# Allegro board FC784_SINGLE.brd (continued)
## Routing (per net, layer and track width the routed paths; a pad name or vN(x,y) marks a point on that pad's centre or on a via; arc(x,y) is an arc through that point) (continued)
IO299: length 3
  TOP w0.127: U1.AC2 41.81,50.23 39.5,50.23
IO300: length 4.4
  TOP w0.254: U1.AC3 v1(42.81,50.23)
  L3_SIG1 w0.102: v1(42.81,50.23) 39.11,50.23
IO301: length 5.6
  TOP w0.254: U1.AC4 v1(43.81,50.23)
  L3_SIG1 w0.102: v1(43.81,50.23) 43.31,49.73 39.11,49.73
IO302: length 7.5
  TOP w0.254: U1.AC6 v1(45.81,50.23)
  L4_SIG2 w0.102: 39.26,49.73 45.02,49.73 45.52,50.23 v1(45.81,50.23)
IO303: length 8.7
  TOP w0.254: U1.AC7 v1(46.81,50.23)
  L4_SIG2 w0.102: 40.49,47.73 45.02,47.73 45.31,48.03 45.31,48.44 45.61,48.73 46.02,48.73 46.31,49.03 46.31,49.44 46.81,49.94 v1(46.81,50.23)
IO304: length 9.5
  TOP w0.254: U1.AC8 v1(47.81,50.23)
  L4_SIG2 w0.102: v1(47.81,50.23) 47.31,49.73 47.31,49.03 47.02,48.73 46.61,48.73 46.31,48.44 46.31,48.03 46.02,47.73 45.61,47.73 45.31,47.44 45.31,46.16 44.62,45.46 44.62,43.23
IO305: length 7.9
  TOP w0.254: U1.AC9 v1(48.81,50.23)
  L4_SIG2 w0.102: 48.31,43.26 48.31,49.73 v1(48.81,50.23)
IO306: length 7.6
  TOP w0.254: U1.AC11 v1(50.81,50.23)
  L5_SIG3 w0.102: v1(50.81,50.23) 50.31,49.73 50.31,45.9 50.84,45.38 50.84,43.77
IO307: length 7.8
  TOP w0.254: U1.AC12 v1(51.81,50.23)
  L4_SIG2 w0.102: 51.31,43.33 51.31,49.73 v1(51.81,50.23)
IO308: length 10.2
  TOP w0.254: U1.AC13 v1(52.81,50.23)
  L4_SIG2 w0.102: 54.31,41.84 54.31,49.47 54.05,49.73 53.31,49.73 v1(52.81,50.23)
IO309: length 9.2
  TOP w0.254: U1.AC14 v1(53.81,50.23)
  L4_SIG2 w0.102: v1(53.81,50.23) 54.77,50.23 55.31,49.69 55.31,46.17 56.07,45.41 56.07,43.23
IO310: length 8
  TOP w0.254: U1.AC16 v1(56.81,50.23)
  L4_SIG2 w0.102: v1(56.81,50.23) 56.31,49.73 56.31,46.09 56.73,45.67 56.73,43.28
IO311: length 8.4
  TOP w0.254: U1.AC17 v1(57.81,50.23)
  L5_SIG3 w0.102: 57.31,42.79 57.31,49.73 v1(57.81,50.23)
IO312: length 8.1
  TOP w0.254: U1.AC18 v1(58.81,50.23)
  L5_SIG3 w0.102: 59.31,43.08 59.31,49.52 58.81,50.02 v1(58.81,50.23)
IO313: length 9
  TOP w0.254: U1.AC19 v1(59.81,50.23)
  L4_SIG2 w0.102: v1(59.81,50.23) 60.31,49.73 60.31,48.03 60.61,47.73 61.02,47.73 61.31,47.44 61.31,42.84
IO314: length 8.4
  TOP w0.254: U1.AC21 v1(61.81,50.23)
  L4_SIG2 w0.102: v1(61.81,50.23) 62.31,49.73 62.31,48.03 62.61,47.73 63.02,47.73 63.31,47.44 63.31,43.44
IO315: length 1.8
  TOP w0.127: U1.AD1 39.5,49.73
IO316: length 4.6
  TOP w0.254: U1.AD3 v1(42.81,49.23)
  L3_SIG1 w0.102: v1(42.81,49.23) 42.52,49.23 41.97,48.69 39.11,48.69
IO317: length 5.8
  TOP w0.254: U1.AD4 v1(43.81,49.23)
  L3_SIG1 w0.102: v1(43.81,49.23) 43.53,49.23 43.03,48.73 42.58,48.73 42.07,48.22 39.11,48.22
IO318: length 7.5
  TOP w0.254: U1.AD5 v1(44.81,49.23)
  L3_SIG1 w0.102: v1(44.81,49.23) 44.31,48.73 43.61,48.73 43.31,48.43 43.31,43.43
IO319: length 7
  TOP w0.254: U1.AD6 v1(45.81,49.23)
  L3_SIG1 w0.102: 45.84,43.37 45.84,45.49 45.31,46.02 45.31,48.73 v1(45.81,49.23)
IO320: length 6.8
  TOP w0.254: U1.AD8 v1(47.81,49.23)
  L4_SIG2 w0.102: v1(47.81,49.23) 47.81,48.94 47.31,48.44 47.31,43.33
IO321: length 6.8
  TOP w0.254: U1.AD9 v1(48.81,49.23)
  L3_SIG1 w0.102: v1(48.81,49.23) 49.31,48.74 49.31,43.31
IO322: length 6.8
  TOP w0.254: U1.AD10 v1(49.81,49.23)
  L4_SIG2 w0.102: v1(49.81,49.23) 49.31,48.73 49.31,43.33
IO323: length 7.1
  TOP w0.254: U1.AD11 v1(50.81,49.23)
  L4_SIG2 w0.102: 50.89,43.27 50.89,45.48 50.31,46.06 50.31,48.73 v1(50.81,49.23)
IO324: length 6.8
  TOP w0.254: U1.AD13 v1(52.81,49.23)
  L4_SIG2 w0.102: v1(52.81,49.23) 53.31,48.73 53.31,43.33
IO325: length 6.7
  TOP w0.254: U1.AD14 v1(53.81,49.23)
  L3_SIG1 w0.102: v1(53.81,49.23) 54.31,48.74 54.31,43.41
IO326: length 7
  TOP w0.254: U1.AD15 v1(55.81,49.23)
  L3_SIG1 w0.102: v1(55.81,49.23) 55.32,48.74 55.32,47.03 55.89,46.46 55.89,43.35
IO327: length 6.8
  TOP w0.254: U1.AD16 v1(56.81,49.23)
  L4_SIG2 w0.102: v1(56.81,49.23) 57.31,48.73 57.31,43.33
IO328: length 7.5
  TOP w0.254: U1.AD18 v1(58.81,49.23)
  L4_SIG2 w0.102: 59.31,43.33 59.31,47.44 59.02,47.73 58.61,47.73 58.31,48.02 58.31,48.73 v1(58.81,49.23)
IO329: length 7.7
  TOP w0.254: U1.AD19 v1(59.81,49.23)
  L4_SIG2 w0.102: 59.75,43.33 59.75,46.34 60.31,46.9 60.31,47.44 60.02,47.73 59.61,47.73 59.31,48.02 59.31,48.73 v1(59.81,49.23)
IO330: length 7
  TOP w0.254: U1.AD20 v1(60.81,49.23)
  L3_SIG1 w0.102: v1(60.81,49.23) 60.32,48.74 60.32,46.22 60.88,45.66 60.88,43.39
IO331: length 7.6
  TOP w0.254: U1.AD21 v1(61.81,49.23)
  L3_SIG1 w0.102: 63.51,43.33 63.51,47.31 63.09,47.73 62.61,47.73 62.31,48.03 62.31,48.73 v1(61.81,49.23)
IO332: length 1.8
  TOP w0.127: U1.AE1 39.5,48.73
IO333: length 3
  TOP w0.127: U1.AE2 41.81,48.23 39.5,48.23
IO334: length 4.6
  TOP w0.254: U1.AE3 v1(42.81,48.23)
  L3_SIG1 w0.102: 39.11,47.75 42.33,47.75 v1(42.81,48.23)
IO335: length 5.5
  TOP w0.254: U1.AE5 v1(44.81,48.23)
  L3_SIG1 w0.102: 44.32,43.68 44.32,47.74 v1(44.81,48.23)
IO336: length 5.8
  TOP w0.254: U1.AE6 v1(45.81,48.23)
  L3_SIG1 w0.102: v1(45.81,48.23) 46.31,47.73 46.31,43.37
IO337: length 5.8
  TOP w0.254: U1.AE7 v1(46.81,48.23)
  L4_SIG2 w0.102: v1(46.81,48.23) 46.81,47.94 46.31,47.44 46.31,43.33
IO338: length 5.8
  TOP w0.254: U1.AE8 v1(47.81,48.23)
  L3_SIG1 w0.102: 47.31,43.37 47.31,47.73 v1(47.81,48.23)
IO339: length 6
  TOP w0.254: U1.AE10 v1(49.81,48.23)
  L3_SIG1 w0.102: 50.84,43.37 50.84,46.43 50.31,46.95 50.31,47.73 v1(49.81,48.23)
IO340: length 5.8
  TOP w0.254: U1.AE11 v1(50.81,48.23)
  L3_SIG1 w0.102: v1(50.81,48.23) 51.31,47.73 51.31,43.37
IO341: length 5.8
  TOP w0.254: U1.AE12 v1(51.81,48.23)
  L3_SIG1 w0.102: v1(51.81,48.23) 52.31,47.73 52.31,43.37
IO342: length 5.8
  TOP w0.254: U1.AE13 v1(52.81,48.23)
  L4_SIG2 w0.102: 52.31,43.33 52.31,47.73 v1(52.81,48.23)
IO343: length 5.8
  TOP w0.254: U1.AE15 v1(55.81,48.23)
  L3_SIG1 w0.102: v1(55.81,48.23) 56.31,47.73 56.31,43.37
IO344: length 5.8
  TOP w0.254: U1.AE16 v1(56.81,48.23)
  L3_SIG1 w0.102: v1(56.81,48.23) 57.31,47.73 57.31,43.37
IO345: length 5.8
  TOP w0.254: U1.AE17 v1(57.81,48.23)
  L4_SIG2 w0.102: v1(57.81,48.23) 57.81,47.94 58.31,47.44 58.31,43.33
IO346: length 5.8
  TOP w0.254: U1.AE18 v1(58.81,48.23)
  L3_SIG1 w0.102: 59.31,43.37 59.31,47.73 v1(58.81,48.23)
IO347: length 5.8
  TOP w0.254: U1.AE20 v1(60.81,48.23)
  L3_SIG1 w0.102: v1(60.81,48.23) 61.31,47.73 61.31,43.37
IO348: length 5.8
  TOP w0.254: U1.AE21 v1(61.81,48.23)
  L3_SIG1 w0.102: 62.31,43.37 62.31,47.45 61.81,47.95 v1(61.81,48.23)
IO349: length 1.8
  TOP w0.127: U1.AF1 39.5,47.73
IO350: length 3
  TOP w0.127: U1.AF2 41.81,47.23 39.5,47.23
IO351: length 4.4
  TOP w0.254: U1.AF3 v1(42.81,47.23)
  L3_SIG1 w0.102: v1(42.81,47.23) 39.11,47.23
IO352: length 4.6
  TOP w0.254: U1.AF4 v1(43.81,47.23)
  L3_SIG1 w0.102: 43.81,43.37 v1(43.81,47.23)
IO353: length 4.7
  TOP w0.254: U1.AF5 v1(44.81,47.23)
  L3_SIG1 w0.102: v1(44.81,47.23) 44.81,43.28
IO354: length 4.6
  TOP w0.254: U1.AF7 v1(46.81,47.23)
  L3_SIG1 w0.102: v1(46.81,47.23) 46.81,43.37
IO355: length 4.8
  TOP w0.254: U1.AF8 v1(47.81,47.23)
  L3_SIG1 w0.102: v1(47.81,47.23) 48.31,46.73 48.31,43.37
IO356: length 4.6
  TOP w0.254: U1.AF9 v1(48.81,47.23)
  L3_SIG1 w0.102: v1(48.81,47.23) 48.81,43.37
IO357: length 4.6
  TOP w0.254: U1.AF10 v1(49.81,47.23)
  L3_SIG1 w0.102: 49.81,43.37 v1(49.81,47.23)
IO358: length 4.6
  TOP w0.254: U1.AF12 v1(51.81,47.23)
  L3_SIG1 w0.102: v1(51.81,47.23) 51.81,43.37
IO359: length 4.8
  TOP w0.254: U1.AF13 v1(52.81,47.23)
  L3_SIG1 w0.102: 53.32,43.37 53.32,46.72 v1(52.81,47.23)
IO360: length 4.6
  TOP w0.254: U1.AF14 v1(53.81,47.23)
  L3_SIG1 w0.102: v1(53.81,47.23) 53.81,43.37
IO361: length 4.6
  TOP w0.254: U1.AF15 v1(54.81,47.23)
  L3_SIG1 w0.102: 54.81,43.37 v1(54.81,47.23)
IO362: length 4.6
  TOP w0.254: U1.AF17 v1(56.81,47.23)
  L3_SIG1 w0.102: v1(56.81,47.23) 56.81,43.37
IO363: length 4.8
  TOP w0.254: U1.AF18 v1(57.81,47.23)
  L3_SIG1 w0.102: v1(57.81,47.23) 58.34,46.71 58.34,43.37
IO364: length 4.6
  TOP w0.254: U1.AF19 v1(58.81,47.23)
  L3_SIG1 w0.102: v1(58.81,47.23) 58.81,43.37
IO365: length 4.6
  TOP w0.254: U1.AF20 v1(59.81,47.23)
  L3_SIG1 w0.102: 59.81,43.37 v1(59.81,47.23)
IO366: length 1.8
  TOP w0.127: U1.AG1 39.5,46.73
IO367: length 3.6
  TOP w0.127: U1.AG2 41.81,46.23 41.81,43.39
IO368: length 3.6
  TOP w0.127: U1.AG4 43.81,46.23 43.81,43.39
IO369: length 3.6
  TOP w0.127: 44.8,43.39 44.8,46.22 U1.AG5
IO370: length 3.6
  TOP w0.127: 45.81,43.39 45.81,46.23 U1.AG6
IO371: length 3.6
  TOP w0.127: 46.81,43.39 46.81,46.23 U1.AG7
IO372: length 3.6
  TOP w0.127: U1.AG9 48.81,46.23 48.81,43.39
IO373: length 3.6
  TOP w0.127: U1.AG10 49.79,46.21 49.79,43.31
IO374: length 3.6
  TOP w0.127: 50.81,43.39 50.81,46.23 U1.AG11
IO375: length 3.6
  TOP w0.127: U1.AG12 51.81,46.23 51.81,43.39
IO376: length 3.6
  TOP w0.127: 53.81,43.39 53.81,46.23 U1.AG14
IO377: length 3.6
  TOP w0.127: U1.AG15 54.83,46.25 54.83,43.3
IO378: length 3.6
  TOP w0.127: U1.AG16 55.81,46.23 55.81,43.39
IO379: length 3.6
  TOP w0.127: U1.AG17 56.81,46.23 56.81,43.39
IO380: length 3.6
  TOP w0.127: 58.81,43.39 58.81,46.23 U1.AG19
IO381: length 3.6
  TOP w0.127: 59.81,43.36 59.81,46.23 U1.AG20
IO382: length 3.6
  TOP w0.127: U1.AG21 60.81,46.23 60.81,43.39
IO383: length 3.6
  TOP w0.127: 61.81,43.39 61.81,46.23 U1.AG22
IO384: length 2.3
  TOP w0.127: U1.AH2 42.31,43.39
IO385: length 2.3
  TOP w0.127: U1.AH3 43.31,43.39
IO386: length 2.3
  TOP w0.127: U1.AH4 44.31,43.39
IO387: length 2.3
  TOP w0.127: U1.AH6 46.31,43.39
IO388: length 2.3
  TOP w0.127: U1.AH7 47.31,43.39
IO389: length 2.3
  TOP w0.127: U1.AH8 48.31,43.39
IO390: length 2.3
  TOP w0.127: U1.AH9 49.31,43.39
IO391: length 2.3
  TOP w0.127: U1.AH11 51.31,43.39
IO392: length 2.3
  TOP w0.127: U1.AH12 52.31,43.39
IO393: length 2.3
  TOP w0.127: U1.AH13 53.31,43.39
IO394: length 2.3
  TOP w0.127: U1.AH14 54.31,43.39
IO395: length 2.3
  TOP w0.127: U1.AH16 56.31,43.39
IO396: length 2.3
  TOP w0.127: U1.AH17 57.31,43.39
IO397: length 2.3
  TOP w0.127: U1.AH18 58.31,43.39
IO398: length 2.3
  TOP w0.127: U1.AH19 59.31,43.39
IO399: length 2.3
  TOP w0.127: U1.AH21 61.31,43.39
IO400: length 2.3
  TOP w0.127: U1.AH22 62.31,43.39
IO401: length 2.3
  TOP w0.127: U1.AH23 63.31,43.39
SERDES_0_INT_REFCLK_N: length 8.4
  TOP w0.254: U1.R24 v1(63.81,59.23)
  L3_SIG1 w0.127: v1(63.81,59.23) 63.55,59.23 63.45,59.13 63.45,58.76 63.56,58.65 66.23,58.65 67.03,59.46 69.95,59.46
SERDES_0_INT_REFCLK_P: length 8.8
  TOP w0.254: U1.R23 v1(62.81,59.23)
  L3_SIG1 w0.127: v1(62.81,59.23) 63.09,59.23 63.17,59.15 63.17,58.65 63.45,58.37 66.34,58.37 67.15,59.18 69.95,59.18
SERDES_0_RX0_N: length 7.5
  TOP w0.254: U1.T26 v1(66.81,57.23)
  L6_SIG4 w0.127: 73.41,57.74 67.49,57.74 67.28,57.53 67.11,57.53 v1(66.81,57.23)
SERDES_0_RX0_P: length 8.6
  TOP w0.254: U1.T25 v1(65.81,57.23)
  L6_SIG4 w0.127: v1(65.81,57.23) 66.41,57.83 67.18,57.83 67.42,58.07 73.41,58.07
SERDES_0_RX1_N: length 7.5
  TOP w0.254: U1.V26 v1(66.81,55.23)
  L6_SIG4 w0.127: 73.41,55.74 67.6,55.74 67.26,55.4 66.98,55.4 v1(66.81,55.23)
SERDES_0_RX1_P: length 8.6
  TOP w0.254: U1.V25 v1(65.81,55.23)
  L6_SIG4 w0.127: 73.41,56.07 67.46,56.07 67.13,55.74 66.32,55.74 v1(65.81,55.23)
SERDES_0_RX2_N: length 7.5
  TOP w0.254: U1.Y26 v1(66.81,53.23)
  L6_SIG4 w0.127: v1(66.81,53.23) 66.98,53.4 67.26,53.4 67.6,53.74 73.41,53.74
SERDES_0_RX2_P: length 8.6
  TOP w0.254: U1.Y25 v1(65.81,53.23)
  L6_SIG4 w0.127: 73.41,54.07 67.46,54.07 67.14,53.75 66.33,53.75 v1(65.81,53.23)
SERDES_0_RX3_N: length 7.5
  TOP w0.254: U1.AB26 v1(66.81,51.23)
  L6_SIG4 w0.127: 73.41,51.74 67.6,51.74 67.23,51.37 66.95,51.37 v1(66.81,51.23)
SERDES_0_RX3_P: length 8.6
  TOP w0.254: U1.AB25 v1(65.81,51.23)
  L6_SIG4 w0.127: v1(65.81,51.23) 66.32,51.74 67.13,51.74 67.46,52.07 73.41,52.07
SERDES_0_TX0_N: length 8.5
  TOP w0.127: 76.62,58.17 69.36,58.17 68.97,58.56 68.48,58.56 U1.R28
SERDES_0_TX0_P: length 9.7
  TOP w0.127: 76.62,57.84 69.22,57.84 68.83,58.23 67.81,58.23 U1.R27
SERDES_0_TX1_N: length 8.5
  TOP w0.127: 76.62,56.17 69.36,56.17 68.97,56.56 68.48,56.56 U1.U28
SERDES_0_TX1_P: length 9.7
  TOP w0.127: 76.62,55.84 69.22,55.84 68.83,56.23 67.81,56.23 U1.U27
SERDES_0_TX2_N: length 8.5
  TOP w0.127: U1.W28 68.48,54.56 68.97,54.56 69.36,54.17 76.62,54.17
SERDES_0_TX2_P: length 9.7
  TOP w0.127: U1.W27 67.81,54.23 68.83,54.23 69.22,53.84 76.62,53.84
SERDES_0_TX3_N: length 8.5
  TOP w0.127: U1.AA28 68.48,52.56 68.97,52.56 69.36,52.17 76.62,52.17
SERDES_0_TX3_P: length 9.7
  TOP w0.127: 76.62,51.84 69.22,51.84 68.83,52.23 67.81,52.23 U1.AA27
SERDES_0N_EXT_REFCLK_N: length 10.9
  TOP w0.254: U1.T22 v1(62.81,57.23)
  L4_SIG2 w0.127: 72.65,58.09 63.67,58.09 v1(62.81,57.23)
SERDES_0N_EXT_REFCLK_P: length 12
  TOP w0.254: U1.T21 v1(61.81,57.23)
  L4_SIG2 w0.127: v1(61.81,57.23) 62.95,58.37 72.65,58.37
SERDES_0S_EXT_REFCLK_N: length 10.7
  TOP w0.254: U1.P22 v1(62.81,60.23)
  L4_SIG2 w0.127: v1(62.81,60.23) 63.31,59.73 66,59.73 66,59.73 66.02,59.73 66.32,59.43 72.47,59.43
SERDES_0S_EXT_REFCLK_P: length 12.6
  TOP w0.254: U1.P21 v1(61.81,60.23)
  L4_SIG2 w0.127: v1(61.81,60.23) 61.81,60.22 62.31,59.72 62.31,59.03 62.61,58.73 66.08,58.73 66.5,59.15 72.47,59.15
SERDES_01_EXT_REFCLK_N: length 8.4
  TOP w0.254: U1.N24 v1(64.81,61.23)
  L4_SIG2 w0.127: v1(64.81,61.23) 65.31,61.73 66.98,61.73 66.98,61.73 67.02,61.73 67.35,61.39 72.17,61.39
SERDES_01_EXT_REFCLK_P: length 9.4
  TOP w0.254: U1.N23 v1(63.81,61.23)
  L4_SIG2 w0.127: 72.17,61.11 67.45,61.11 67.05,60.71 64.34,60.71 v1(63.81,61.23)
SERDES_1_INT_REFCLK_N: length 9.7
  TOP w0.254: U1.M22 v1(62.81,62.23)
  L5_SIG3 w0.127: v1(62.81,62.23) 63.31,62.73 69.14,62.73 69.46,62.41 71.43,62.41
SERDES_1_INT_REFCLK_P: length 10.7
  TOP w0.254: U1.M21 v1(61.81,62.23)
  L5_SIG3 w0.127: 71.43,62.13 69.44,62.13 69.01,61.7 62.34,61.7 v1(61.81,62.23)
SERDES_1_RX0_N: length 8.7
  TOP w0.254: U1.H25 v1(65.81,66.23)
  L6_SIG4 w0.127: v1(65.81,66.23) 66.34,65.71 67.15,65.71 67.7,65.16 73.41,65.16
SERDES_1_RX0_P: length 7.6
  TOP w0.254: U1.H26 v1(66.81,66.23)
  L6_SIG4 w0.127: 73.41,65.49 67.84,65.49 67.24,66.08 66.96,66.08 v1(66.81,66.23)
SERDES_1_RX1_N: length 8.7
  TOP w0.254: U1.K25 v1(65.81,64.23)
  L6_SIG4 w0.127: 73.41,63.16 67.7,63.16 67.16,63.7 66.35,63.7 v1(65.81,64.23)
SERDES_1_RX1_P: length 7.6
  TOP w0.254: U1.K26 v1(66.81,64.23)
  L6_SIG4 w0.127: 73.41,63.49 67.84,63.49 67.26,64.06 66.98,64.06 v1(66.81,64.23)
SERDES_1_RX2_N: length 8.7
  TOP w0.254: U1.M25 v1(65.81,62.23)
  L6_SIG4 w0.127: v1(65.81,62.23) 66.33,61.72 67.14,61.72 67.7,61.16 73.41,61.16
SERDES_1_RX2_P: length 7.6
  TOP w0.254: U1.M26 v1(66.81,62.23)
  L6_SIG4 w0.127: v1(66.81,62.23) 67.09,62.23 67.84,61.49 73.41,61.49
SERDES_1_RX3_N: length 8.6
  TOP w0.254: U1.P25 v1(65.81,60.23)
  L6_SIG4 w0.127: 73.41,59.4 67.46,59.4 67.16,59.7 66.35,59.7 v1(65.81,60.23)
SERDES_1_RX3_P: length 7.5
  TOP w0.254: U1.P26 v1(66.81,60.23)
  L6_SIG4 w0.127: 73.41,59.73 67.6,59.73 67.26,60.06 66.98,60.06 v1(66.81,60.23)
SERDES_1_TX0_N: length 9.7
  TOP w0.127: 76.62,67.62 69.22,67.62 68.83,67.23 67.81,67.23 U1.G27
SERDES_1_TX0_P: length 8.5
  TOP w0.127: U1.G28 68.48,66.9 68.97,66.9 69.36,67.29 76.62,67.29
SERDES_1_TX1_N: length 9.7
  TOP w0.127: U1.J27 67.81,65.23 68.83,65.23 69.22,65.62 76.62,65.62
SERDES_1_TX1_P: length 8.5
  TOP w0.127: 76.62,65.29 69.36,65.29 68.97,64.9 68.48,64.9 U1.J28
SERDES_1_TX2_N: length 9.7
  TOP w0.127: 76.62,63.62 69.22,63.62 68.83,63.23 67.81,63.23 U1.L27
SERDES_1_TX2_P: length 8.5
  TOP w0.127: U1.L28 68.48,62.9 68.97,62.9 69.36,63.29 76.62,63.29
SERDES_1_TX3_N: length 9.7
  TOP w0.127: U1.N27 67.81,61.23 68.83,61.23 69.22,61.62 76.62,61.62
SERDES_1_TX3_P: length 8.5
  TOP w0.127: U1.N28 68.48,60.9 68.97,60.9 69.36,61.29 76.62,61.29
SERDES_02_EXT_REFCLK_N: length 9
  TOP w0.254: U1.U24 v1(64.81,56.23)
  L4_SIG2 w0.127: 72.75,57.05 69.33,57.05 69.02,56.73 65.31,56.73 v1(64.81,56.23)
SERDES_02_EXT_REFCLK_P: length 10.8
  TOP w0.254: U1.U23 v1(63.81,56.23)
  L4_SIG2 w0.127: v1(63.81,56.23) 64.31,56.73 64.31,57.44 64.61,57.74 69.01,57.74 69.42,57.33 72.75,57.33
SERDES_2_INT_REFCLK_N: length 8.8
  TOP w0.254: U1.W24 v1(64.81,54.23)
  L4_SIG2 w0.127: v1(64.81,54.23) 65.31,54.73 68.99,54.73 69,54.74 69.02,54.74 69.39,55.11 72.53,55.11
SERDES_2_INT_REFCLK_P: length 10.5
  TOP w0.254: U1.W23 v1(63.81,54.23)
  L4_SIG2 w0.127: 72.53,55.39 69.4,55.39 69.12,55.67 64.6,55.67 64.31,55.38 64.31,54.73 v1(63.81,54.23)
SERDES_2_RX0_N: length 10.7
  TOP w0.254: U1.AC23 v1(63.81,50.23)
  L6_SIG4 w0.127: 73.4,50.15 67.65,50.15 67.23,49.73 64.32,49.73 v1(63.81,50.23)
SERDES_2_RX0_P: length 9.6
  TOP w0.254: U1.AC24 v1(64.81,50.23)
  L6_SIG4 w0.127: 73.4,50.48 67.52,50.48 67.31,50.69 65.27,50.69 v1(64.81,50.23)
SERDES_2_RX1_N: length 7.6
  TOP w0.254: U1.AF26 v1(66.81,47.23)
  L6_SIG4 w0.127: v1(66.81,47.23) 66.98,47.06 67.26,47.06 67.84,46.49 73.41,46.49
SERDES_2_RX1_P: length 8.7
  TOP w0.254: U1.AF25 v1(65.81,47.23)
  L6_SIG4 w0.127: 73.41,46.16 67.7,46.16 67.14,46.72 66.33,46.72 v1(65.81,47.23)
SERDES_2_RX2_N: length 7.6
  TOP w0.254: U1.AD26 v1(66.81,49.23)
  L6_SIG4 w0.127: 73.41,48.49 67.84,48.49 67.26,49.06 66.98,49.06 v1(66.81,49.23)
SERDES_2_RX2_P: length 8.7
  TOP w0.254: U1.AD25 v1(65.81,49.23)
  L6_SIG4 w0.127: v1(65.81,49.23) 66.33,48.72 67.14,48.72 67.7,48.16 73.41,48.16
SERDES_2_RX3_N: length 14.2
  TOP w0.254: U1.AE24 v1(64.81,48.23)
  L6_SIG4 w0.127: v1(64.81,48.23) 64.43,47.85 64.43,47.62 64.03,47.22 64.03,44.81 64.5,44.34 73.55,44.34
SERDES_2_RX3_P: length 14.7
  TOP w0.254: U1.AE23 v1(63.81,48.23)
  L6_SIG4 w0.127: v1(63.81,48.23) 64.1,47.94 64.1,47.76 63.7,47.36 63.7,44.67 64.36,44.01 73.55,44.01
SERDES_2_TX0_N: length 8.5
  TOP w0.127: 76.62,50.17 69.36,50.17 68.97,50.56 68.48,50.56 U1.AC28
SERDES_2_TX0_P: length 9.7
  TOP w0.127: 76.62,49.84 69.22,49.84 68.83,50.23 67.81,50.23 U1.AC27
SERDES_2_TX1_N: length 12.1
  TOP w0.127: 76.62,44.11 66.49,44.11 65.98,44.62 65.98,45.4 U1.AH26
SERDES_2_TX1_P: length 12.7
  TOP w0.127: U1.AH25 65.65,45.4 65.65,44.49 66.35,43.78 76.62,43.78
SERDES_2_TX2_N: length 8.5
  TOP w0.127: U1.AE28 68.48,48.56 68.97,48.56 69.36,48.17 76.62,48.17
SERDES_2_TX2_P: length 9.7
  TOP w0.127: U1.AE27 67.81,48.23 68.83,48.23 69.22,47.84 76.62,47.84
SERDES_2_TX3_N: length 8.5
  TOP w0.127: U1.AG28 68.48,46.56 68.97,46.56 69.36,46.17 76.62,46.17
SERDES_2_TX3_P: length 9.7
  TOP w0.127: 76.62,45.84 69.22,45.84 68.83,46.23 67.81,46.23 U1.AG27
SERDES_3_INT_REFCLK_N: length 8.2
  TOP w0.254: U1.J24 v1(64.81,65.23)
  L4_SIG2 w0.127: 71.98,66.09 69.49,66.09 69.13,65.73 65.61,65.73 65.11,65.23 v1(64.81,65.23)
SERDES_3_INT_REFCLK_P: length 9.9
  TOP w0.254: U1.J23 v1(63.81,65.23)
  L4_SIG2 w0.127: 71.98,66.37 69.44,66.37 69.08,66.73 65.61,66.73 65.31,66.44 65.31,65.96 65.1,65.75 64.34,65.75 63.82,65.23 v1(63.81,65.23)
SERDES_3_RX0_N: length 9
  TOP w0.254: U1.B25 v1(65.81,72.23)
  L6_SIG4 w0.127: v1(65.81,72.23) 66.19,72.61 66.19,72.9 66.72,73.43 73.41,73.43
SERDES_3_RX0_P: length 8.4
  TOP w0.254: U1.B26 v1(66.81,72.23)
  L6_SIG4 w0.127: 73.41,73.1 66.86,73.1 66.52,72.76 66.52,72.52 v1(66.81,72.23)
SERDES_3_RX1_N: length 8.7
  TOP w0.254: U1.D25 v1(65.81,70.23)
  L6_SIG4 w0.127: 73.41,71.31 67.7,71.31 67.17,70.78 66.36,70.78 v1(65.81,70.23)
SERDES_3_RX1_P: length 7.6
  TOP w0.254: U1.D26 v1(66.81,70.23)
  L6_SIG4 w0.127: 73.41,70.98 67.84,70.98 67.26,70.4 66.98,70.4 v1(66.81,70.23)
SERDES_3_RX2_N: length 13.6
  TOP w0.254: U1.C23 v1(63.81,71.23)
  L6_SIG4 w0.127: 73.28,74.99 64.84,74.99 63.79,73.94 63.79,72.06 64.15,71.7 64.15,71.57 v1(63.81,71.23)
SERDES_3_RX2_P: length 13.1
  TOP w0.254: U1.C24 v1(64.81,71.23)
  L6_SIG4 w0.127: v1(64.81,71.23) 64.48,71.57 64.48,71.84 64.12,72.19 64.12,73.8 64.98,74.66 73.28,74.66
SERDES_3_RX3_N: length 8.7
  TOP w0.254: U1.F25 v1(65.81,68.23)
  L6_SIG4 w0.127: v1(65.81,68.23) 66.33,67.72 67.14,67.72 67.7,67.16 73.41,67.16
SERDES_3_RX3_P: length 7.6
  TOP w0.254: U1.F26 v1(66.81,68.23)
  L6_SIG4 w0.127: 73.41,67.49 67.84,67.49 67.26,68.06 66.98,68.06 v1(66.81,68.23)
SERDES_3_TX0_N: length 9.6
  TOP w0.127: 75.75,74.65 68.54,74.65 67.65,73.75 67.65,73.07 U1.A27
SERDES_3_TX0_P: length 9.1
  TOP w0.127: U1.A28 67.98,73.07 67.98,73.62 68.68,74.32 75.75,74.32
SERDES_3_TX1_N: length 9.7
  TOP w0.127: U1.C27 67.81,71.23 68.83,71.23 69.22,71.62 76.62,71.62
SERDES_3_TX1_P: length 8.5
  TOP w0.127: U1.C28 68.48,70.9 68.97,70.9 69.36,71.29 76.62,71.29
SERDES_3_TX2_N: length 14.3
  TOP w0.127: 75.82,75.98 65.85,75.98 63.65,73.78 63.65,73.07 U1.A23
SERDES_3_TX2_P: length 13.7
  TOP w0.127: 75.82,75.65 65.99,75.65 63.98,73.64 63.98,73.07 U1.A24
SERDES_3_TX3_N: length 9.7
  TOP w0.127: 76.62,69.62 69.22,69.62 68.83,69.23 67.81,69.23 U1.E27
SERDES_3_TX3_P: length 8.5
  TOP w0.127: 76.62,69.29 69.36,69.29 68.97,68.9 68.48,68.9 U1.E28
SERDES_13_EXT_REFCLK_N: length 8.4
  TOP w0.254: U1.L24 v1(64.81,63.23)
  L4_SIG2 w0.127: 72.16,63.43 67.42,63.43 67.12,63.73 65.31,63.73 v1(64.81,63.23)
SERDES_13_EXT_REFCLK_P: length 9.5
  TOP w0.254: U1.L23 v1(63.81,63.23)
  L4_SIG2 w0.127: 72.16,63.15 67.49,63.15 67.05,62.71 64.34,62.71 v1(63.81,63.23)
SERDES_24_EXT_REFCLK_N: length 9.1
  TOP w0.254: U1.AA24 v1(64.81,52.23)
  L4_SIG2 w0.127: 72.81,51.37 69.41,51.37 69.05,51.73 65.61,51.73 65.11,52.23 v1(64.81,52.23)
SERDES_24_EXT_REFCLK_P: length 10.8
  TOP w0.254: U1.AA23 v1(63.81,52.23)
  L4_SIG2 w0.127: 72.81,51.09 69.4,51.09 69.05,50.73 65.52,50.73 65.31,50.94 65.31,51.46 65.06,51.72 64.54,51.72 64.02,52.23 v1(63.81,52.23)
SERDES_35_EXT_REFCLK_N: length 8.8
  TOP w0.254: U1.G24 v1(64.81,67.23)
  L4_SIG2 w0.127: v1(64.81,67.23) 64.81,67.48 65.31,67.98 65.31,68.44 65.61,68.73 66.89,68.73 67.3,69.15 71.68,69.15
SERDES_35_EXT_REFCLK_P: length 10.4
  TOP w0.254: U1.G23 v1(63.81,67.23)
  L4_SIG2 w0.127: v1(63.81,67.23) 63.81,67.24 64.31,67.74 64.31,68.44 64.61,68.73 65.02,68.73 65.31,69.03 65.31,69.44 65.61,69.73 66.95,69.73 67.25,69.43 71.68,69.43
SERDES_VREF: length 1.4
  TOP w0.254: U1.F22 v1(62.81,68.23) ; U1.H22 v1(62.81,66.23)

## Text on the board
BOTTOM: Layer 14 (BOTTOM)
Ref Des/Assembly Bottom: ASSEMBLY_BOTTOM
Ref Des/Silkscreen Bottom: 305-PD-1X-XXXX | MICROSEMI TECHNICAL SUPPORT | +1(800) 262-1060
TOP: Layer 1 (TOP)
Ref Des/Assembly Top: ASSEMBLY_TOP
Ref Des/Silkscreen Top: RT4G_DEVELOPMENT_KIT REV A | DVP-101-000XXX-001
FAB_DATA: 4.0 MILS | 6.5 MILS | 50 OHM | SINGLE | 3.5/8.0 MILS | DIFFERENTIAL | 5 / 8 MILS | 100 OHM | 5.1 / 4.9 MILS | 90 OHM | REV | 1 | INTIAL RELEASE | DESCRIPTION | REVISIONS | XXXXXXXX | DATE | APPROVAL | 10.  VIAS IN THIS REGION NEEDS VIA PLUGGING FROM BOTTOM SIDE. | 14.  IMPEDANCE TOLERANCE SHOULD BE +/- 5% ON L1, L12, L14. REST OF THE LAYRES CAN HAVE 10% TOLERANCE | 11.  BOARD MUST BE UL 94V-1 APPROVED. | 12.  FABRICATE BOARD PER IPC-A-600D STANDARD. | 13.  CLIP SILKSCREEN ON NO MASK AREA. | 17.  REMOVE UNUSED PADS IN ALL INNER LAYERS. | 18.  BOARD DIMENSIONS ARE IN INCHES | 15.  NO VENDOR LOGO, ART WORKS SHOULD NOT BE | 20.  THIS IS A ROHS COMPLIANT BOARD | 19.  WARP & TWIST: SHALL NOT EXCEED 0.005 INCHES PER INCH | 2.1. SELECTIVE HARD GOLD PLATING TO BE FLAT & | 16.  DEBURR ALL SHARP EDGES | 21.  EDGE FINGER- CHAMFER EDGES MUST BE FREE OF CUTTING BURRS | 5.  SILKSCREEN BOTH SIDES, WHITE. | 7.  SOLDER MASK TOP AND BOTTOM SIDES WITH | 6.  FABRICATE PER DIMENSIONS SHOWN. | PLATING IN HOLES TO BE 0.001 MIN. THICK. | 4.  HOLE SIZES ARE AFTER PLATING. | 3.  HOLES TO BE PLATED THROUGH. | 9.  APPLY THIEVING AS REQUIRED. | 8.  TOTAL BOARD THICKNESS:  62 mil+/- 6 mil | SOLDER MASK.  COLOR GREEN. | LIQUID PHOTO IMAGABLE OR DRY FILM | 14 LAYER CONSTRUCTION. | 2.  GENERAL PLATING - FLASH GOLD | NOTES: UNLESS OTHERWISE SPECIFIED | 1.  MATERIAL: FR-4. | ABOVE THE SOLDER RESIST SURFACE ON TOP AND BOTTOM | THE VIAS SHOULD BE SMOOTHENED TO BOARD SURFACE ON TOP AND BOTTOM | GOLD PLATING ON PAD SHOULD BE THE SAME LEVEL OR | FOR SELECTIVE PLATING SEE BELOW | CHANGED WITHOUT PRIOR APPROVAL FROM PACTRON | PLATED 30uIN(MINIMUM) OF Au OVER 150-200uIN OF Ni. | NOTE: DIELECTRIC GLASS STYLE SHOULD NOT BE CHANGED WITHOUT PRIOR APPROVAL FROM PACTRON. | GLASS STYLE | DIELECTRIC | SHOULD NOT BE CHANGED FROM ABOVE STATED VALUES. | FINISHED TRACE WIDTH,AIR GAP OF 100 OHM DIFFERENTIAL AND 50 OHM SIGNLE ENDED | 2116 | STACKUP - 14 LAYERS | REFER STACKUP | CONTROLLED IMPEDANCE REQUIRED
User.17: FIGURE | SIZE | 125.0 | DRILL CHART: TOP to BOTTOM | ALL UNITS ARE IN MILS | TOLERANCE | +2.0/-2.0 | PLATED | NON-PLATED | QTY | 2
User.19: DATE: | FILM LAYER: | NAME: | XXXXXXXX | XXXXXXXXXXXXXXXXXXXX | REV: | A | PACTRON
User.20: FAB | PROJECT NAME | PART NUMBER | PACTRON | DATE | 3000 PATRICK HENRY DRIVE, SANTA CLARA, CA 95054. | 408-329-5500(PHONE), 408-747-1239(FAX). | XXXXXXXXXXXXXXXXXXXXXX | DVP-101-000XXX-001 | XXXXXXXX | 305-PD-15-XXXX | REV : | A
User.23: DIELECTRIC (4.00 mils) | DIELECTRIC (4.50 mils) | DIELECTRIC (3.50 mils) | DIELECTRIC (2.00 mils) | TOP (1.40 mils) | L2_GND1 (0.60 mils) | L3_SIG1 (0.60 mils) | L4_GND2 (0.60 mils) | L5_SIG2 (0.60 mils) | L6_GND3 (0.60 mils) | L7_PWR1 (1.30 mils) | L8_PWR2 (1.30 mils) | L9_GND4 (0.60 mils) | L10_SIG3 (0.60 mils) | L11_GND5 (0.60 mils) | L12_SIG4 (0.60 mils) | L13_GND6 (0.60 mils) | BOTTOM (1.40 mils) | FR-4
